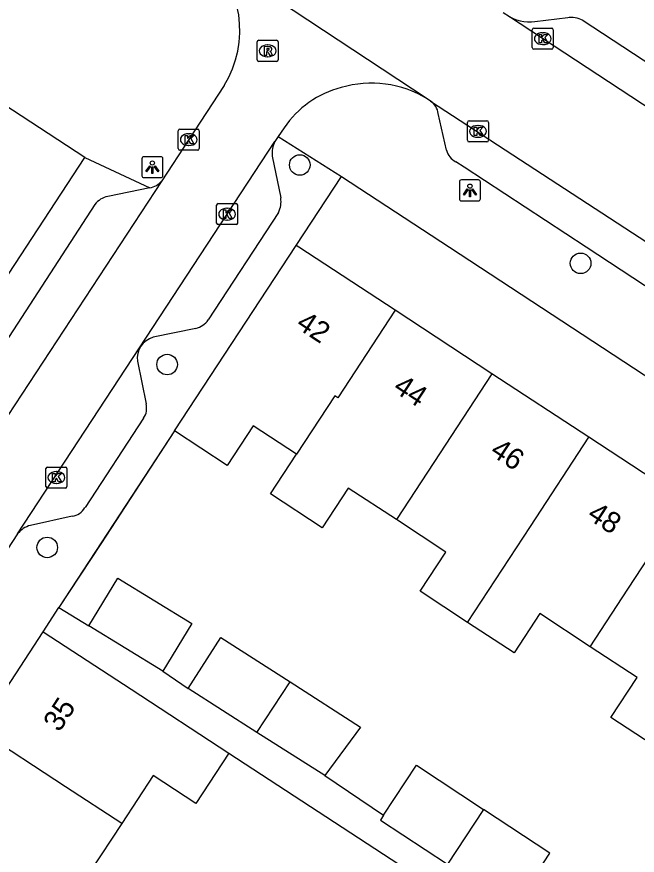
# Model space of a CAD drawing. Extents: x 159280 to 160375, y 384531 to 385872.
# Drawn here: x 159791.01 to 159820.5, y 384971.07 to 385010.96 of the extents above; entities that cross this region are included whole.
import ezdxf

# ---------------------------------------------------------------- set-up
doc = ezdxf.new("R2010")
doc.units = 0
for name, color, linetype in [('IMGEO_Boom', 7, 'Continuous'), ('IMGEO_Kolk', 7, 'Continuous'), ('IMGEO_Lichtpunt', 7, 'Continuous'), ('IMGEO_Muur', 7, 'Continuous'), ('IMGEO_Pand', 7, 'Continuous'), ('IMGEO_Pand_nummerreeks', 7, 'Continuous'), ('IMGEO_Rijbaan_lokaal_open', 7, 'Continuous'), ('IMGEO_Rioolput', 7, 'Continuous'), ('IMGEO_Voetpad_open', 7, 'Continuous')]:
    doc.layers.add(name, color=color, linetype=linetype)

msp = doc.modelspace()

# ---------------------------------------------------------------- linework, layer by layer
at = {"layer": 'IMGEO_Boom'}
for centre in [(159804.462, 385003.913), (159817.812, 384999.235), (159798.155, 384994.419), (159792.457, 384985.717)]:
    msp.add_circle(centre, 0.489, dxfattribs=at)
at = {"layer": 'IMGEO_Kolk'}
for p, q in [((159815.514, 385009.497), (159815.514, 385010.349)), ((159815.589, 385010.423), (159816.441, 385010.423)), ((159816.002, 385010.203), (159816.027, 385010.203)), ((159816.515, 385010.349), (159816.515, 385009.497)), ((159816.441, 385009.423), (159815.589, 385009.423)), ((159816.025, 385009.643), (159816, 385009.643)), ((159812.434, 385005.086), (159812.434, 385005.938)), ((159812.509, 385006.012), (159813.361, 385006.012)), ((159812.922, 385005.792), (159812.947, 385005.792)), ((159813.435, 385005.938), (159813.435, 385005.086)), ((159798.686, 385004.693), (159798.686, 385005.545)), ((159798.761, 385005.619), (159799.613, 385005.619)), ((159799.174, 385005.399), (159799.199, 385005.399)), ((159799.687, 385005.545), (159799.687, 385004.693)), ((159813.361, 385005.012), (159812.509, 385005.012)), ((159812.945, 385005.232), (159812.92, 385005.232)), ((159799.613, 385004.619), (159798.761, 385004.619)), ((159799.197, 385004.839), (159799.172, 385004.839)), ((159800.509, 385001.148), (159800.509, 385002)), ((159800.584, 385002.074), (159801.436, 385002.074)), ((159800.997, 385001.854), (159801.022, 385001.854)), ((159801.51, 385002), (159801.51, 385001.148)), ((159801.436, 385001.074), (159800.584, 385001.074)), ((159801.02, 385001.294), (159800.995, 385001.294)), ((159792.393, 384988.617), (159792.393, 384989.469)), ((159792.468, 384989.543), (159793.32, 384989.543)), ((159793.394, 384989.469), (159793.394, 384988.617)), ((159792.881, 384989.323), (159792.906, 384989.323)), ((159792.904, 384988.763), (159792.879, 384988.763)), ((159793.32, 384988.543), (159792.468, 384988.543))]:
    msp.add_line(p, q, dxfattribs=at)
for points in [[(159815.514, 385009.497), (159815.514, 385010.349)], [(159815.589, 385010.423), (159816.441, 385010.423)], [(159815.835, 385010.123), (159815.958, 385010.123), (159815.958, 385009.972), (159816.088, 385010.123), (159816.252, 385010.123), (159816.106, 385009.972), (159816.259, 385009.723), (159816.107, 385009.723), (159816.022, 385009.887), (159815.958, 385009.82), (159815.958, 385009.723), (159815.835, 385009.723), (159815.835, 385010.123)], [(159816.515, 385010.349), (159816.515, 385009.497)], [(159816.441, 385009.423), (159815.589, 385009.423)], [(159812.434, 385005.086), (159812.434, 385005.938)], [(159812.509, 385006.012), (159813.361, 385006.012)], [(159813.435, 385005.938), (159813.435, 385005.086)], [(159798.686, 385004.693), (159798.686, 385005.545)], [(159798.761, 385005.619), (159799.613, 385005.619)], [(159799.687, 385005.545), (159799.687, 385004.693)], [(159812.755, 385005.712), (159812.878, 385005.712), (159812.878, 385005.561), (159813.008, 385005.712), (159813.172, 385005.712), (159813.026, 385005.561), (159813.179, 385005.312), (159813.027, 385005.312), (159812.942, 385005.476), (159812.878, 385005.409), (159812.878, 385005.312), (159812.755, 385005.312), (159812.755, 385005.712)], [(159799.007, 385005.319), (159799.13, 385005.319), (159799.13, 385005.168), (159799.26, 385005.319), (159799.424, 385005.319), (159799.278, 385005.168), (159799.431, 385004.919), (159799.279, 385004.919), (159799.194, 385005.083), (159799.13, 385005.016), (159799.13, 385004.919), (159799.007, 385004.919), (159799.007, 385005.319)], [(159813.361, 385005.012), (159812.509, 385005.012)], [(159799.613, 385004.619), (159798.761, 385004.619)], [(159800.509, 385001.148), (159800.509, 385002)], [(159800.584, 385002.074), (159801.436, 385002.074)], [(159800.83, 385001.774), (159800.953, 385001.774), (159800.953, 385001.623), (159801.083, 385001.774), (159801.247, 385001.774), (159801.101, 385001.623), (159801.254, 385001.374), (159801.102, 385001.374), (159801.017, 385001.538), (159800.953, 385001.471), (159800.953, 385001.374), (159800.83, 385001.374), (159800.83, 385001.774)], [(159801.51, 385002), (159801.51, 385001.148)], [(159801.436, 385001.074), (159800.584, 385001.074)], [(159792.393, 384988.617), (159792.393, 384989.469)], [(159792.468, 384989.543), (159793.32, 384989.543)], [(159793.394, 384989.469), (159793.394, 384988.617)], [(159792.714, 384989.243), (159792.837, 384989.243), (159792.837, 384989.092), (159792.967, 384989.243), (159793.131, 384989.243), (159792.985, 384989.092), (159793.138, 384988.843), (159792.986, 384988.843), (159792.901, 384989.007), (159792.837, 384988.94), (159792.837, 384988.843), (159792.714, 384988.843), (159792.714, 384989.243)], [(159793.32, 384988.543), (159792.468, 384988.543)]]:
    msp.add_lwpolyline(points, dxfattribs=at)
for centre, start, end in [((159815.591, 385010.347), 91.552, 178.448), ((159815.591, 385010.347), 91.552, 178.448), ((159816.439, 385010.347), 1.552, 88.448), ((159816.439, 385010.347), 1.552, 88.448), ((159815.591, 385009.499), 181.552, 268.448), ((159815.591, 385009.499), 181.552, 268.448), ((159816.439, 385009.499), 271.552, 358.448), ((159816.439, 385009.499), 271.552, 358.448), ((159812.511, 385005.936), 91.552, 178.448), ((159812.511, 385005.936), 91.552, 178.448), ((159813.359, 385005.936), 1.552, 88.448), ((159813.359, 385005.936), 1.552, 88.448), ((159798.763, 385005.543), 91.552, 178.448), ((159798.763, 385005.543), 91.552, 178.448), ((159799.611, 385005.543), 1.552, 88.448), ((159799.611, 385005.543), 1.552, 88.448), ((159812.511, 385005.088), 181.552, 268.448), ((159812.511, 385005.088), 181.552, 268.448), ((159813.359, 385005.088), 271.552, 358.448), ((159813.359, 385005.088), 271.552, 358.448), ((159798.763, 385004.695), 181.552, 268.448), ((159798.763, 385004.695), 181.552, 268.448), ((159799.611, 385004.695), 271.552, 358.448), ((159799.611, 385004.695), 271.552, 358.448), ((159800.586, 385001.998), 91.552, 178.448), ((159800.586, 385001.998), 91.552, 178.448), ((159801.434, 385001.998), 1.552, 88.448), ((159801.434, 385001.998), 1.552, 88.448), ((159800.586, 385001.15), 181.552, 268.448), ((159800.586, 385001.15), 181.552, 268.448), ((159801.434, 385001.15), 271.552, 358.448), ((159801.434, 385001.15), 271.552, 358.448), ((159792.47, 384989.467), 91.552, 178.448), ((159792.47, 384989.467), 91.552, 178.448), ((159793.318, 384989.467), 1.552, 88.448), ((159793.318, 384989.467), 1.552, 88.448), ((159792.47, 384988.619), 181.552, 268.448), ((159792.47, 384988.619), 181.552, 268.448), ((159793.318, 384988.619), 271.552, 358.448), ((159793.318, 384988.619), 271.552, 358.448)]:
    msp.add_arc(centre, 0.0765, start, end, dxfattribs=at)
for centre, major_axis, ratio, start_param, end_param in [((159816.001, 385009.923), (-0.387, 0.002), 0.722429, 4.712389, 7.853982), ((159816.026, 385009.923), (-0.39, 0.002), 0.717154, 1.570796, 4.712389), ((159812.921, 385005.512), (-0.387, 0.002), 0.722429, 4.712389, 7.853982), ((159812.946, 385005.512), (-0.39, 0.002), 0.717154, 1.570796, 4.712389), ((159799.173, 385005.119), (-0.387, 0.002), 0.722429, 4.712389, 7.853982), ((159799.198, 385005.119), (-0.39, 0.002), 0.717154, 1.570796, 4.712389), ((159800.996, 385001.574), (-0.387, 0.002), 0.722429, 4.712389, 7.853982), ((159801.021, 385001.574), (-0.39, 0.002), 0.717154, 1.570796, 4.712389), ((159792.88, 384989.043), (-0.387, 0.002), 0.722429, 4.712389, 7.853982), ((159792.905, 384989.043), (-0.39, 0.002), 0.717154, 1.570796, 4.712389)]:
    msp.add_ellipse(centre, major_axis=major_axis, ratio=ratio, start_param=start_param, end_param=end_param, dxfattribs=at)
at = {"layer": 'IMGEO_Lichtpunt'}
for p, q in [((159796.958, 385004.211), (159796.958, 385003.404)), ((159796.958, 385004.211), (159796.958, 385003.404)), ((159797.86, 385004.306), (159797.052, 385004.306)), ((159797.86, 385004.306), (159797.052, 385004.306)), ((159797.954, 385003.404), (159797.954, 385004.211)), ((159797.954, 385003.404), (159797.954, 385004.211)), ((159797.052, 385003.31), (159797.86, 385003.31)), ((159797.052, 385003.31), (159797.86, 385003.31)), ((159812.052, 385003.109), (159812.052, 385002.302)), ((159812.052, 385003.109), (159812.052, 385002.302)), ((159812.954, 385003.204), (159812.146, 385003.204)), ((159812.954, 385003.204), (159812.146, 385003.204)), ((159813.048, 385002.302), (159813.048, 385003.109)), ((159813.048, 385002.302), (159813.048, 385003.109)), ((159812.146, 385002.208), (159812.954, 385002.208)), ((159812.146, 385002.208), (159812.954, 385002.208))]:
    msp.add_line(p, q, dxfattribs=at)
for points in [[(159797.332, 385003.875), (159797.371, 385003.847), (159797.183, 385003.585), (159797.145, 385003.612), (159797.332, 385003.875)], [(159797.434, 385003.827), (159797.481, 385003.827), (159797.481, 385003.505), (159797.434, 385003.505), (159797.434, 385003.827)], [(159797.544, 385003.847), (159797.582, 385003.874), (159797.769, 385003.612), (159797.73, 385003.584), (159797.544, 385003.847)], [(159812.426, 385002.773), (159812.465, 385002.745), (159812.277, 385002.483), (159812.239, 385002.51), (159812.426, 385002.773)], [(159812.528, 385002.725), (159812.575, 385002.725), (159812.575, 385002.403), (159812.528, 385002.403), (159812.528, 385002.725)], [(159812.638, 385002.745), (159812.676, 385002.772), (159812.863, 385002.51), (159812.824, 385002.482), (159812.638, 385002.745)]]:
    msp.add_lwpolyline(points, dxfattribs=at)
for centre in [(159797.457, 385004.009), (159812.551, 385002.907)]:
    msp.add_circle(centre, 0.0994, dxfattribs=at)
for centre, start, end in [((159797.052, 385004.211), 90, 180), ((159797.052, 385004.211), 90, 180), ((159797.86, 385004.211), 0, 90), ((159797.86, 385004.211), 0, 90), ((159797.052, 385003.404), 180, 270), ((159797.052, 385003.404), 180, 270), ((159797.86, 385003.404), 270, 0), ((159797.86, 385003.404), 270, 360), ((159812.146, 385003.109), 90, 180), ((159812.146, 385003.109), 90, 180), ((159812.954, 385003.109), 0, 90), ((159812.954, 385003.109), 0, 90), ((159812.146, 385002.302), 180, 270), ((159812.146, 385002.302), 180, 270), ((159812.954, 385002.302), 270, 0), ((159812.954, 385002.302), 270, 360)]:
    msp.add_arc(centre, 0.0946, start, end, dxfattribs=at)
at = {"layer": 'IMGEO_Muur'}
msp.add_lwpolyline([(159798.5, 384991.258), (159793.016, 384982.856)], dxfattribs=at)
at = {"layer": 'IMGEO_Pand'}
for points in [[(159794.238, 385004.267), (159762.408, 385025.116)], [(159789.786, 384997.476), (159794.238, 385004.267)], [(159798.5, 384991.258), (159804.289, 385000.083)], [(159808.992, 384996.998), (159804.416, 385000), (159804.289, 385000.083)], [(159808.992, 384996.998), (159806.266, 384992.834), (159806.124, 384992.927), (159804.305, 384990.154)], [(159813.598, 384993.976), (159808.992, 384996.998)], [(159813.598, 384993.976), (159810.836, 384989.759), (159809.054, 384987.039)], [(159818.202, 384990.956), (159813.598, 384993.976)], [(159804.305, 384990.154), (159802.252, 384991.5), (159801.012, 384989.61), (159798.5, 384991.258)], [(159812.438, 384982.153), (159815.425, 384986.714), (159818.202, 384990.956)], [(159822.808, 384987.934), (159818.202, 384990.956)], [(159809.054, 384987.039), (159806.767, 384988.539), (159805.533, 384986.657), (159803.07, 384988.272), (159804.305, 384990.154)], [(159818.264, 384980.997), (159820.053, 384983.728), (159822.808, 384987.934)], [(159812.438, 384982.153), (159810.183, 384983.632), (159811.406, 384985.496), (159809.054, 384987.039)], [(159794.432, 384981.989), (159795.82, 384984.256), (159799.334, 384982.105), (159797.946, 384979.838)], [(159818.264, 384980.997), (159815.87, 384982.568), (159814.647, 384980.704), (159812.438, 384982.153)], [(159797.946, 384979.838), (159794.432, 384981.989)], [(159789.206, 384977.032), (159792.266, 384981.707)], [(159792.266, 384981.707), (159796.45, 384978.969), (159801.094, 384975.929)], [(159799.162, 384979), (159800.704, 384981.437), (159803.999, 384979.32)], [(159821.624, 384976.075), (159819.257, 384977.628), (159820.504, 384979.528), (159818.264, 384980.997)], [(159802.427, 384976.919), (159803.999, 384979.32)], [(159803.999, 384979.32), (159807.346, 384977.169), (159805.651, 384974.865)], [(159802.427, 384976.919), (159799.162, 384979)], [(159795.999, 384972.585), (159793.333, 384974.33), (159789.206, 384977.032)], [(159805.651, 384974.865), (159802.427, 384976.919)], [(159801.094, 384975.929), (159799.528, 384973.536), (159797.493, 384974.868), (159795.999, 384972.585)], [(159808.448, 384972.981), (159810.004, 384975.353), (159813.191, 384973.252)], [(159813.191, 384973.252), (159811.489, 384970.655)], [(159814.75, 384968.738), (159816.352, 384971.169), (159813.191, 384973.252)], [(159808.448, 384972.981), (159808.296, 384972.749), (159811.489, 384970.655)], [(159795.999, 384972.585), (159794.506, 384970.304), (159796.481, 384969.012), (159794.91, 384966.611)]]:
    msp.add_lwpolyline(points, dxfattribs=at)
at = {"layer": 'IMGEO_Rijbaan_lokaal_open'}
for points in [[(159810.522, 385007.053), (159799.912, 385014.064)], [(159814.439, 385010.956), (159814.137, 385011.155)], [(159837.547, 384995.775), (159814.439, 385010.956)], [(159800.869, 385007.687), (159799.187, 385005.119), (159797.9, 385003.158)], [(159810.677, 385006.951), (159810.522, 385007.053)], [(159810.677, 385006.951), (159821.323, 385000), (159834.587, 384991.28)], [(159803.728, 385005.677), (159803.442, 385005.261)], [(159791.048, 384986.363), (159803.284, 385005.031)], [(159803.442, 385005.261), (159803.284, 385005.031)], [(159797.9, 385003.158), (159788.908, 384989.457)], [(159791.048, 384986.363), (159788.002, 384981.726)]]:
    msp.add_lwpolyline(points, dxfattribs=at)
for centre, radius, start, end in [((159796.626, 385010.311), 4.988, 328.2692, 48.8002), ((159807.876, 385002.768), 5.036, 58.3087, 106.6416), ((159807.533, 385003.173), 4.555, 103.9561, 146.6451)]:
    msp.add_arc(centre, radius, start, end, dxfattribs=at)
at = {"layer": 'IMGEO_Rioolput'}
for p, q in [((159802.436, 385008.917), (159802.436, 385009.769)), ((159802.511, 385009.843), (159803.363, 385009.843)), ((159803.437, 385009.769), (159803.437, 385008.917)), ((159802.924, 385009.623), (159802.949, 385009.623)), ((159802.947, 385009.063), (159802.922, 385009.063)), ((159803.363, 385008.843), (159802.511, 385008.843))]:
    msp.add_line(p, q, dxfattribs=at)
for points in [[(159802.436, 385008.917), (159802.436, 385009.769)], [(159802.511, 385009.843), (159803.363, 385009.843)], [(159803.437, 385009.769), (159803.437, 385008.917)], [(159803.025, 385009.541), (159802.773, 385009.543), (159802.773, 385009.143)], [(159802.951, 385009.462), (159802.897, 385009.462), (159802.897, 385009.381)], [(159802.897, 385009.381), (159802.949, 385009.381)], [(159802.773, 385009.143), (159802.897, 385009.143), (159802.897, 385009.305), (159802.908, 385009.305)], [(159802.955, 385009.276), (159803.026, 385009.143), (159803.166, 385009.143), (159803.101, 385009.269)], [(159803.363, 385008.843), (159802.511, 385008.843)]]:
    msp.add_lwpolyline(points, dxfattribs=at)
for centre, radius, start, end in [((159802.513, 385009.767), 0.0765, 91.552, 178.448), ((159802.513, 385009.767), 0.0765, 91.552, 178.448), ((159803.361, 385009.767), 0.0765, 1.552, 88.448), ((159803.361, 385009.767), 0.0765, 1.552, 88.448), ((159802.933, 385009.57), 0.19, 274.7715, 282.9687), ((159802.957, 385009.366), 0.0964, 77.0061, 93.1865), ((159802.971, 385009.423), 0.0378, 276.6634, 79.6772), ((159803.024, 385009.431), 0.109, 350.3612, 89.416), ((159803.022, 385009.431), 0.112, 277.5842, 350.9817), ((159802.907, 385009.252), 0.0533, 26.0293, 88.6989), ((159803.006, 385009.216), 0.108, 29.5134, 73.7905), ((159802.513, 385008.919), 0.0765, 181.552, 268.448), ((159802.513, 385008.919), 0.0765, 181.552, 268.448), ((159803.361, 385008.919), 0.0765, 271.552, 358.448), ((159803.361, 385008.919), 0.0765, 271.552, 358.448)]:
    msp.add_arc(centre, radius, start, end, dxfattribs=at)
for centre, major_axis, ratio, start_param, end_param in [((159802.923, 385009.343), (-0.387, 0.002), 0.722429, 4.712389, 7.853982), ((159802.948, 385009.343), (-0.39, 0.002), 0.717154, 1.570796, 4.712389)]:
    msp.add_ellipse(centre, major_axis=major_axis, ratio=ratio, start_param=start_param, end_param=end_param, dxfattribs=at)
at = {"layer": 'IMGEO_Voetpad_open'}
for points in [[(159814.439, 385010.956), (159814.6, 385010.878), (159814.768, 385010.816), (159814.941, 385010.768), (159815.117, 385010.736), (159815.295, 385010.72), (159815.475, 385010.72), (159815.632, 385010.733), (159817.208, 385010.93), (159817.276, 385010.94), (159817.366, 385010.945), (159817.457, 385010.943), (159817.548, 385010.932), (159817.637, 385010.913), (159817.724, 385010.887), (159817.808, 385010.853), (159817.889, 385010.811), (159834.363, 385000), (159838.529, 384997.266)], [(159811.437, 385004.613), (159811.048, 385006.359)], [(159803.442, 385005.261), (159806.445, 385003.369)], [(159794.238, 385004.267), (159797.331, 385002.832)], [(159803.154, 385004.34), (159803.559, 385002.344)], [(159833.608, 384989.793), (159818.079, 385000), (159812.281, 385003.811), (159811.878, 385004.067)], [(159804.289, 385000.083), (159806.445, 385003.369)], [(159806.445, 385003.369), (159811.579, 385000), (159857.297, 384969.998)], [(159797.331, 385002.832), (159795.335, 385002.415)], [(159794.726, 385002.037), (159788.695, 384992.765)], [(159803.452, 385001.658), (159800.11, 384996.538)], [(159799.519, 384996.132), (159797.499, 384995.716)], [(159796.744, 384994.575), (159797.154, 384992.556)], [(159797.037, 384991.868), (159794.253, 384987.614)], [(159798.5, 384991.258), (159794.998, 384985.893), (159793.016, 384982.856)], [(159793.642, 384987.202), (159791.661, 384986.764)], [(159792.266, 384981.707), (159793.016, 384982.856)], [(159793.016, 384982.856), (159794.432, 384981.989)], [(159797.946, 384979.838), (159799.162, 384979)], [(159801.094, 384975.929), (159809.577, 384970.376)], [(159805.651, 384974.865), (159808.448, 384972.981)]]:
    msp.add_lwpolyline(points, dxfattribs=at)
for centre, radius, start, end in [((159810.186, 385006.231), 0.871, 8.4417, 55.7082), ((159804.326, 385004.477), 1.18, 152.0153, 186.6753), ((159812.308, 385004.865), 0.907, 196.1545, 241.7006), ((159797.233, 385003.662), 0.835, 276.7031, 322.9167), ((159795.541, 385001.404), 1.032, 101.5049, 142.15), ((159802.452, 385002.165), 1.121, 333.0956, 9.1737), ((159799.224, 384997.195), 1.103, 285.5232, 323.4527), ((159797.771, 384994.715), 1.037, 105.2294, 187.7853), ((159796.382, 384992.333), 0.803, 324.5986, 16.0989), ((159793.534, 384988.021), 0.826, 277.5137, 330.4702), ((159791.92, 384985.699), 1.096, 103.6622, 142.72)]:
    msp.add_arc(centre, radius, start, end, dxfattribs=at)

# ---------------------------------------------------------------- texts
at = {"layer": 'IMGEO_Pand_nummerreeks'}
for s, rotation, p in [('42', 326.7345, (159804.229, 384996.2)), ('44', 326.7345, (159808.844, 384993.173)), ('46', 326.7345, (159813.455, 384990.148)), ('48', 326.7345, (159818.069, 384987.12)), ('35', 56.7941, (159793.034, 384976.891))]:
    msp.add_text(s, height=1, rotation=rotation, dxfattribs=at).set_placement(p)

doc.saveas('drawing.dxf')
